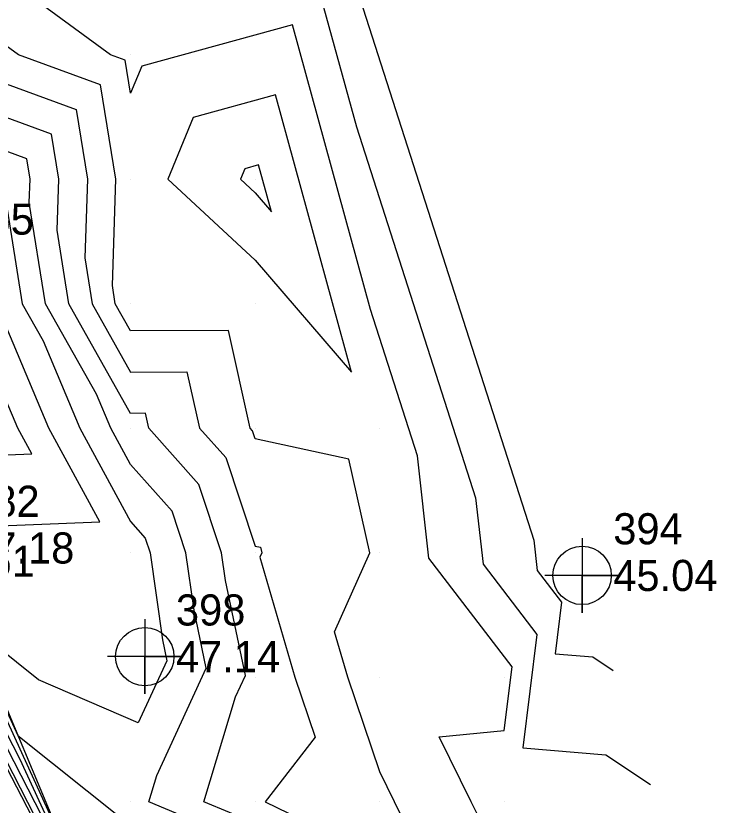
# Model space of a CAD drawing. Extents: x 2090860 to 2091277, y 159470 to 160080.
# Drawn here: x 2091170.8 to 2091227, y 159599.7 to 159663.1 of the extents above; entities that cross this region are included whole.
import ezdxf

# ---------------------------------------------------------------- set-up
doc = ezdxf.new("R2010")
doc.units = 0
for name, color, linetype in [('DTM Contours Major', 7, 'Continuous'), ('DTM Contours Minor', 7, 'Continuous'), ('Exist DTM Breakline', 7, 'Continuous'), ('Exist DTM Breakline Cogo Elevation', 7, 'Continuous'), ('Exist DTM Breakline Cogo Number', 7, 'Continuous'), ('Exist DTM QL2 LIDAR Elevation Point', 7, 'Continuous'), ('Exist DTM Regular Point CELL', 7, 'Continuous'), ('Exist DTM Regular Point Cogo Elevation', 7, 'Continuous'), ('Exist DTM Regular Point Cogo Number', 7, 'Continuous')]:
    doc.layers.add(name, color=color, linetype=linetype)

msp = doc.modelspace()

# ---------------------------------------------------------------- linework, layer by layer
at = {"layer": 'DTM Contours Major'}
for points in [[(2091202.349, 159597.651), (2091201.178, 159600), (2091200, 159602.396), (2091197.432, 159610), (2091196.367, 159613.633), (2091199.218, 159620), (2091197.516, 159627.516), (2091190, 159629.161), (2091189.791, 159629.791), (2091189.605, 159630), (2091187.846, 159637.846), (2091180, 159637.819), (2091178.769, 159640), (2091178.535, 159641.465), (2091178.822, 159650), (2091177.59, 159657.59), (2091170.983, 159660), (2091170, 159660.722)], [(2091191.634, 159656.779), (2091185.03, 159654.97), (2091182.985, 159650), (2091190, 159643.5), (2091197.744, 159634.512), (2091191.634, 159656.779)], [(2091170, 159648.096), (2091171.297, 159640), (2091172.975, 159637.025), (2091175.918, 159630), (2091180, 159622.502), (2091181.177, 159621.177), (2091181.569, 159620), (2091182.562, 159612.995), (2091182.914, 159611.32), (2091180.616, 159606.324), (2091172.606, 159609.793), (2091167.266, 159614.052)], [(2091162.224, 159619.585), (2091172.872, 159598.824), (2091175.683, 159592.701), (2091177.053, 159590.039), (2091177.994, 159587.927), (2091182.697, 159577.853), (2091190.683, 159560.736), (2091193.182, 159555.38), (2091195.125, 159551.216), (2091203.298, 159535.129), (2091208.815, 159524.502), (2091210.513, 159521.162), (2091212.364, 159517.603), (2091212.599, 159516.124), (2091218.269, 159517.951), (2091225.533, 159506.041)]]:
    msp.add_lwpolyline(points, dxfattribs=at)
at = {"layer": 'DTM Contours Minor'}
for points in [[(2091160, 159717.218), (2091172.816, 159725.36), (2091172.93, 159709.849), (2091174.594, 159687.678), (2091173.73, 159679.526), (2091185.967, 159672.414), (2091185.557, 159665.633), (2091194.348, 159668.04), (2091198.143, 159654.212), (2091207.702, 159624.397), (2091208.298, 159619.068), (2091212.623, 159613.426), (2091211.487, 159604.317), (2091218.172, 159603.765), (2091221.756, 159601.382)], [(2091187.469, 159699.242), (2091188.879, 159680.457), (2091188.581, 159677.64), (2091192.809, 159675.182), (2091192.668, 159672.839), (2091195.705, 159673.671), (2091197.017, 159668.893), (2091212.372, 159621), (2091212.643, 159618.58), (2091214.607, 159616.017), (2091214.091, 159611.881), (2091217.127, 159611.63), (2091218.755, 159610.548)], [(2091224.758, 159592.216), (2091219.216, 159595.899), (2091213.64, 159596.36), (2091210, 159594.685), (2091207.351, 159600), (2091204.789, 159605.211), (2091210, 159605.717), (2091210.638, 159610.834), (2091203.954, 159619.556), (2091203.032, 159627.795), (2091199.269, 159639.531), (2091192.991, 159662.41), (2091180.902, 159659.098), (2091180, 159656.907), (2091179.568, 159659.568), (2091178.384, 159660), (2091170, 159666.162)], [(2091170, 159657.659), (2091175.612, 159655.612), (2091176.523, 159650), (2091176.31, 159643.69), (2091176.901, 159640), (2091180, 159634.508), (2091184.524, 159634.524), (2091185.538, 159630), (2091187.637, 159627.637), (2091190, 159620.528), (2091190.433, 159620.433), (2091190.532, 159620), (2091190.367, 159619.633), (2091193.192, 159610), (2091194.819, 159605.181), (2091190.813, 159600), (2091200, 159595.519)], [(2091190, 159598.264), (2091185.89, 159600), (2091188.433, 159608.433), (2091189.22, 159610.145), (2091187.624, 159617.762), (2091187.307, 159620), (2091185.484, 159625.484), (2091181.471, 159630), (2091181.201, 159631.201), (2091180, 159631.197), (2091175.033, 159640), (2091174.086, 159645.914), (2091174.223, 159650), (2091173.633, 159653.633), (2091170, 159654.959)], [(2091190, 159596.394), (2091181.463, 159600), (2091182.094, 159602.094), (2091186.067, 159610.732), (2091185.093, 159615.379), (2091184.438, 159620), (2091183.331, 159623.331), (2091180, 159627.079), (2091178.409, 159630), (2091177.263, 159632.737), (2091173.165, 159640), (2091171.861, 159648.139), (2091171.924, 159650), (2091171.655, 159651.655), (2091170, 159652.259)], [(2091190.277, 159651.149), (2091189.158, 159650.842), (2091188.811, 159650), (2091190, 159648.899), (2091191.312, 159647.376), (2091190.277, 159651.149)], [(2091173.426, 159630), (2091170, 159638.18), (2091160.501, 159630.672), (2091165.512, 159621.989), (2091177.521, 159622.479), (2091173.426, 159630)], [(2091170.935, 159630), (2091170, 159632.232), (2091167.408, 159630.183), (2091168.775, 159627.814), (2091172.052, 159627.948), (2091170.935, 159630)], [(2091219.632, 159519.564), (2091212.693, 159517.327), (2091212.629, 159517.725), (2091209.731, 159523.297), (2091209.075, 159524.588), (2091200.413, 159541.27), (2091195.327, 159551.282), (2091192.243, 159557.89), (2091190.868, 159560.838), (2091186.473, 159570.258), (2091178.174, 159588.034), (2091176.514, 159591.761), (2091176.021, 159592.717), (2091171.123, 159603.387), (2091162.729, 159619.754)], [(2091161.719, 159619.417), (2091174.621, 159594.26), (2091175.344, 159592.685), (2091177.593, 159588.317), (2091177.814, 159587.82), (2091178.922, 159585.448), (2091190.498, 159560.635), (2091194.121, 159552.871), (2091194.924, 159551.15), (2091206.182, 159528.988), (2091208.556, 159524.417), (2091211.295, 159519.027), (2091212.099, 159517.481), (2091212.506, 159514.92), (2091216.907, 159516.339), (2091222.545, 159507.094)], [(2091167.626, 159612.514), (2091170.933, 159605.31), (2091179.293, 159598.642)], [(2091169.375, 159607.95), (2091174.599, 159596.569)]]:
    msp.add_lwpolyline(points, dxfattribs=at)
at = {"layer": 'Exist DTM Breakline'}
for points in [[(2091104.06, 159746.702), (2091118.019, 159713.353), (2091131.537, 159686.371), (2091144.554, 159657.113), (2091164.611, 159620.381), (2091178.178, 159588.037), (2091195.659, 159551.391), (2091212.727, 159517.77)], [(2091103.084, 159746.105), (2091115.591, 159711.787), (2091128.144, 159684.602), (2091142.549, 159655.707), (2091161.438, 159619.323), (2091177.759, 159587.787), (2091194.782, 159551.104), (2091211.895, 159517.387)]]:
    msp.add_lwpolyline(points, dxfattribs=at)
at = {"layer": 'Exist DTM QL2 LIDAR Elevation Point'}
for p, q in [((2091180, 159660), (2091180, 159660)), ((2091180, 159650), (2091180, 159650)), ((2091190, 159650), (2091190, 159650)), ((2091180, 159640), (2091180, 159640)), ((2091190, 159640), (2091190, 159640)), ((2091180, 159630), (2091180, 159630)), ((2091190, 159630), (2091190, 159630)), ((2091200, 159630), (2091200, 159630)), ((2091180, 159620), (2091180, 159620)), ((2091190, 159620), (2091190, 159620)), ((2091200, 159620), (2091200, 159620)), ((2091190, 159610), (2091190, 159610)), ((2091200, 159610), (2091200, 159610)), ((2091210, 159610), (2091210, 159610)), ((2091180, 159600), (2091180, 159600)), ((2091190, 159600), (2091190, 159600)), ((2091200, 159600), (2091200, 159600)), ((2091210, 159600), (2091210, 159600))]:
    msp.add_line(p, q, dxfattribs=at)
at = {"layer": 'Exist DTM Regular Point CELL'}
for points in [[(2091216.258, 159621.174), (2091216.258, 159615.174), (2091216.258, 159618.174), (2091219.258, 159618.174), (2091213.258, 159618.174)], [(2091181.135, 159614.651), (2091181.135, 159608.651), (2091181.135, 159611.651), (2091184.135, 159611.651), (2091178.135, 159611.651)]]:
    msp.add_lwpolyline(points, dxfattribs=at)
for centre in [(2091216.258, 159618.174), (2091181.135, 159611.651)]:
    msp.add_circle(centre, 2.344, dxfattribs=at)

# ---------------------------------------------------------------- texts
at = {"layer": 'Exist DTM Breakline Cogo Elevation'}
for s, p in [('47.18', (2091167.111, 159619.131)), ('45.61', (2091163.938, 159618.073))]:
    msp.add_text(s, height=2.5, dxfattribs=at).set_placement(p)
at = {"layer": 'Exist DTM Breakline Cogo Number'}
msp.add_text('382', height=2.5, dxfattribs=at).set_placement((2091167.111, 159622.881))
at = {"layer": 'Exist DTM Regular Point Cogo Elevation'}
for s, p in [('47.65', (2091163.857, 159645.551)), ('45.04', (2091218.758, 159616.924)), ('47.14', (2091183.635, 159610.401))]:
    msp.add_text(s, height=2.5, dxfattribs=at).set_placement(p)
at = {"layer": 'Exist DTM Regular Point Cogo Number'}
for s, p in [('394', (2091218.758, 159620.674)), ('398', (2091183.635, 159614.151))]:
    msp.add_text(s, height=2.5, dxfattribs=at).set_placement(p)

doc.saveas('drawing.dxf')
